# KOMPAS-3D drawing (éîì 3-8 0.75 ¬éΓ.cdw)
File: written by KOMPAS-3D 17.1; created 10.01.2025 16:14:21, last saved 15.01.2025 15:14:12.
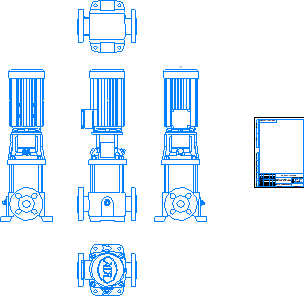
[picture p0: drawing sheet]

Sheet 1: A4, portrait

Title block, sheet 1: name: ВМН 3-8 0.75 кВт; designation: ВМН 3-8 0.75 кВт; material: Сталь 10  ГОСТ 1050-2013; mass: 68,16; sheets: 1; sheet format: A4; stored path: \\adlc.lan\data\АДЛ_ПКД\3D-модели\ADL production\Насосы ГРАНПАМП\Насосы ВМН\ВМН3\KOMPAS 3D\3-8 0.75 кВт _ ВМН.cdw

Views: Вид 1, Спереди, Проекционный вид 2, Проекционный вид 3, Проекционный вид 4, Проекционный вид 5
Referenced files in \\adlc.lan\data\АДЛ_ПКД\3D-модели\ADL production\Насосы ГРАНПАМП\Насосы ВМН\ВМН3\KOMPAS 3D\: ВМН 3-8 0,75 кВт.m3d
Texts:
  Andrey
  АДЛ
Dimensions and other numbers on the sheet: 1:1; 1; 68,16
